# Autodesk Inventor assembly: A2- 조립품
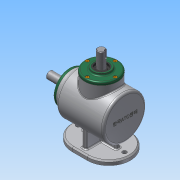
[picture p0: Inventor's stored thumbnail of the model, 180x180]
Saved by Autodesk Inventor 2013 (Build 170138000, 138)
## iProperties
Created: 2016-04
Part Number: A2- 조립품
Document SubType Name: Assembly
Designer: Administrator
Author: Administrator
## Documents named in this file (14)
- C:\Users\Administrator\Desktop\460408V1002\A2- 조립품.iam
- C:\Users\Administrator\Desktop\460408V1002\1 - 본체.ipt
- C:\Users\Administrator\Desktop\460408V1002\오일실 17 32 8.ipt
- C:\Users\Administrator\Desktop\460408V1002\커버.ipt
- C:\Users\Administrator\Desktop\460408V1002\베어링 6203.ipt
- C:\Users\Administrator\Desktop\460408V1002\메인 축.ipt
- 메인 축.ipt
- C:\Users\Administrator\Desktop\460408V1002\서브 축.ipt
- 서브 축.ipt
- C:\Users\Administrator\Desktop\460408V1002\서브 베벨기어.ipt
- C:\Users\Administrator\Desktop\460408V1002\키 4x4.ipt
- C:\Users\Administrator\Desktop\460408V1002\키 5x5.ipt
- C:\Users\Administrator\Desktop\460408V1002\메인 베벨기어.ipt
- C:\Users\Administrator\Desktop\460408V1002\M4.ipt
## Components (9 placed, 2 different names)
1. 1 - 본체:1
2. M4:1
3. M4:3
4. M4:4
5. M4:5
6. M4:2
7. M4:6
8. M4:7
9. M4:8
